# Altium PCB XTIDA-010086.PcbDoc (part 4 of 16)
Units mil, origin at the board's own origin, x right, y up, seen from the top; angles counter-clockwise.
Board outline 14763.78 x 8267.72 mil, 6 copper layers (Top Layer, GND Layer, Signal Layer 1, Signal Layer 2, Power Layer, Bottom Layer), stack 62 mil thick; 1933 components, 1002 nets, 4886 pads, 6482 vias.
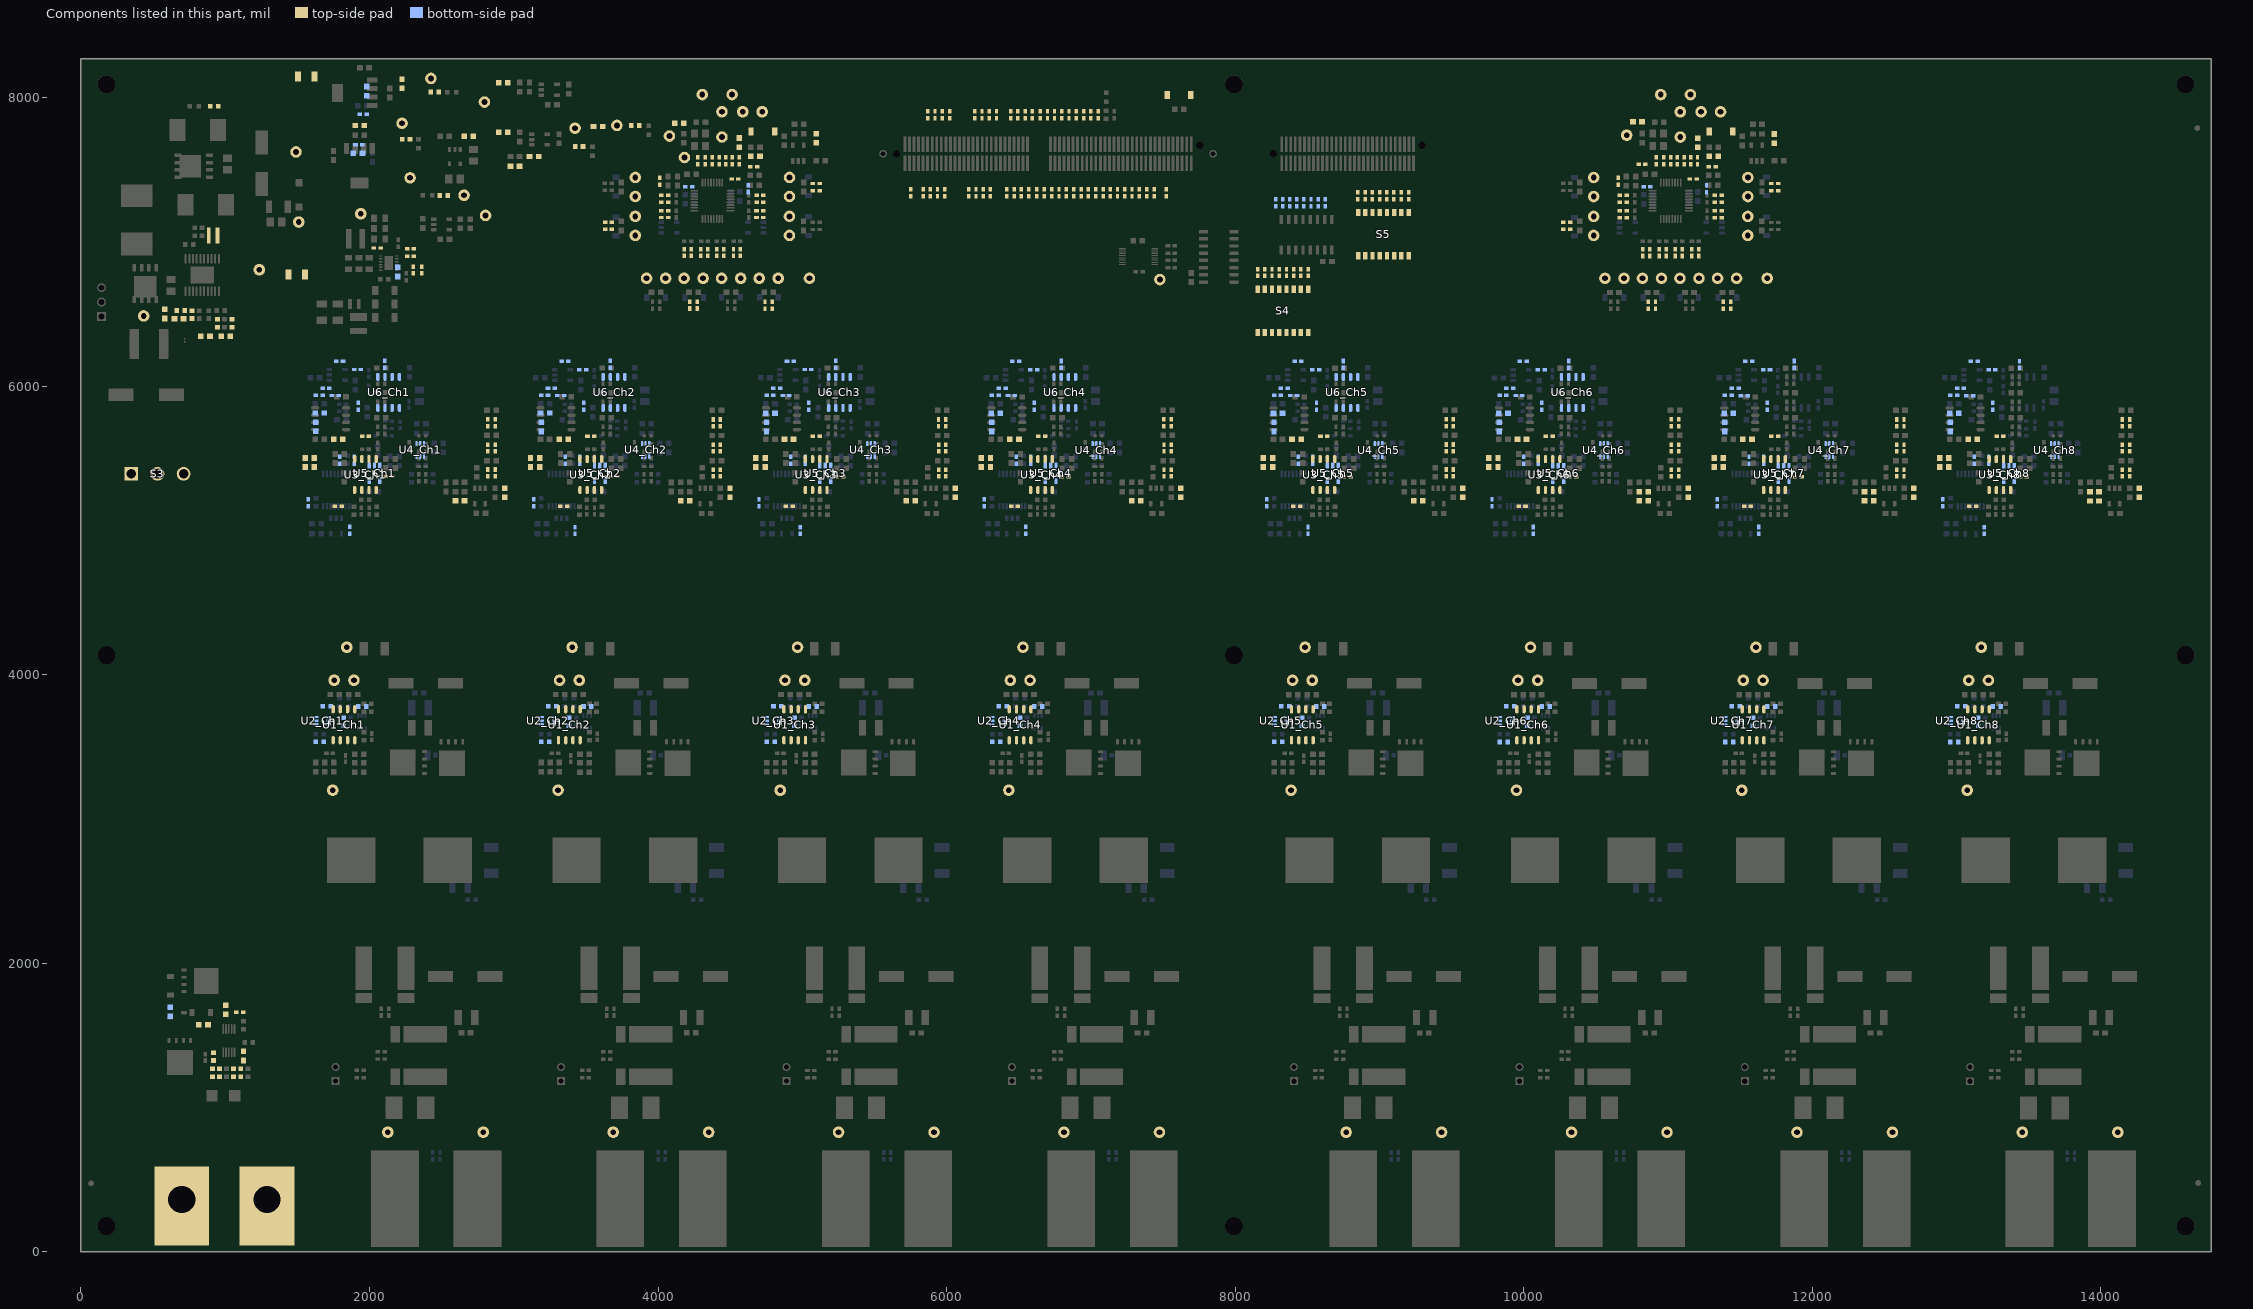
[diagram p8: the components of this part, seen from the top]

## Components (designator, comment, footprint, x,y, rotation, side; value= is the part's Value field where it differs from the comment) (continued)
R64_Ch6 "RT0603BRD07100KL" 0603 10831.24,5267.91 r0 top value=100k (schematic designator R64)
R64_Ch7 "RT0603BRD07100KL" 0603 12393.24,5267.83 r0 top value=100k (schematic designator R64)
R64_Ch8 "RT0603BRD07100KL" 0603 13955.24,5267.75 r0 top value=100k (schematic designator R64)
R65_Ch1 "PNM0402E5000BST1" 0402 2871,5398.08 r90 top value=500 (schematic designator R65)
R65_Ch2 "PNM0402E5000BST1" 0402 4432.54,5397.54 r90 top value=500 (schematic designator R65)
R65_Ch3 "PNM0402E5000BST1" 0402 5994.54,5397.46 r90 top value=500 (schematic designator R65)
R65_Ch4 "PNM0402E5000BST1" 0402 7556.6,5397.93 r90 top value=500 (schematic designator R65)
R65_Ch5 "PNM0402E5000BST1" 0402 9512.29,5398.24 r90 top value=500 (schematic designator R65)
R65_Ch6 "PNM0402E5000BST1" 0402 11073.3,5397.77 r90 top value=500 (schematic designator R65)
R65_Ch7 "PNM0402E5000BST1" 0402 12635.3,5397.69 r90 top value=500 (schematic designator R65)
R65_Ch8 "PNM0402E5000BST1" 0402 14198.3,5397.62 r90 top value=500 (schematic designator R65)
R66_Ch1 "PNM0402E5000BST1" 0402 2871,5571.08 r90 top value=500 (schematic designator R66)
R66_Ch2 "PNM0402E5000BST1" 0402 4432.54,5570.54 r90 top value=500 (schematic designator R66)
R66_Ch3 "PNM0402E5000BST1" 0402 5994.54,5570.46 r90 top value=500 (schematic designator R66)
R66_Ch4 "PNM0402E5000BST1" 0402 7556.6,5570.93 r90 top value=500 (schematic designator R66)
R66_Ch5 "PNM0402E5000BST1" 0402 9512.29,5571.24 r90 top value=500 (schematic designator R66)
R66_Ch6 "PNM0402E5000BST1" 0402 11073.3,5570.77 r90 top value=500 (schematic designator R66)
R66_Ch7 "PNM0402E5000BST1" 0402 12635.3,5570.69 r90 top value=500 (schematic designator R66)
R66_Ch8 "PNM0402E5000BST1" 0402 14198.3,5570.62 r90 top value=500 (schematic designator R66)
R67_Ch1 "PNM0402E5000BST1" 0402 2871,5745.08 r90 top value=500 (schematic designator R67)
R67_Ch2 "PNM0402E5000BST1" 0402 4432.54,5744.54 r90 top value=500 (schematic designator R67)
R67_Ch3 "PNM0402E5000BST1" 0402 5994.54,5744.46 r90 top value=500 (schematic designator R67)
R67_Ch4 "PNM0402E5000BST1" 0402 7556.6,5744.93 r90 top value=500 (schematic designator R67)
R67_Ch5 "PNM0402E5000BST1" 0402 9512.29,5745.24 r90 top value=500 (schematic designator R67)
R67_Ch6 "PNM0402E5000BST1" 0402 11073.3,5744.77 r90 top value=500 (schematic designator R67)
R67_Ch7 "PNM0402E5000BST1" 0402 12635.3,5744.69 r90 top value=500 (schematic designator R67)
R67_Ch8 "PNM0402E5000BST1" 0402 14198.3,5744.62 r90 top value=500 (schematic designator R67)
R68_Ch1 "PNM0402E5000BST1" 0402 3656.85,7085.68 r0 top value=500 (schematic designator R68)
R68_Ch2 "PNM0402E5000BST1" 0402 4271.03,6561.02 r90 top value=500 (schematic designator R68)
R68_Ch3 "PNM0402E5000BST1" 0402 4791.7,6560.09 r90 top value=500 (schematic designator R68)
R68_Ch4 "PNM0402E5000BST1" 0402 5097,7403.98 r180 top value=500 (schematic designator R68)
R68_Ch5 "PNM0402E5000BST1" 0402 10298.55,7085.37 r0 top value=500 (schematic designator R68)
R68_Ch6 "PNM0402E5000BST1" 0402 10912.73,6560.71 r90 top value=500 (schematic designator R68)
R68_Ch7 "PNM0402E5000BST1" 0402 11433.15,6560.71 r90 top value=500 (schematic designator R68)
R68_Ch8 "PNM0402E5000BST1" 0402 11738.7,7403.67 r180 top value=500 (schematic designator R68)
R69_Ch1 "CRCW06033K32FKEA" 0603 1628,5717.5 r270 bottom value=3.32k (schematic designator R69)
R69_Ch2 "CRCW06033K32FKEA" 0603 3189.55,5716.98 r270 bottom value=3.32k (schematic designator R69)
R69_Ch3 "CRCW06033K32FKEA" 0603 4751.55,5716.9 r270 bottom value=3.32k (schematic designator R69)
R69_Ch4 "CRCW06033K32FKEA" 0603 6313.55,5716.82 r270 bottom value=3.32k (schematic designator R69)
R69_Ch5 "CRCW06033K32FKEA" 0603 8269.25,5716.74 r270 bottom value=3.32k (schematic designator R69)
R69_Ch6 "CRCW06033K32FKEA" 0603 9831.25,5716.66 r270 bottom value=3.32k (schematic designator R69)
R69_Ch7 "CRCW06033K32FKEA" 0603 11393.25,5716.58 r270 bottom value=3.32k (schematic designator R69)
R69_Ch8 "CRCW06033K32FKEA" 0603 12955.7,5716.95 r270 bottom value=3.32k (schematic designator R69)
R70_Ch1 "RT0603BRD07100KL" 0603 2627.54,5204.3 r0 top value=100k (schematic designator R70)
R70_Ch2 "RT0603BRD07100KL" 0603 4189.54,5204.22 r0 top value=100k (schematic designator R70)
R70_Ch3 "RT0603BRD07100KL" 0603 5751.54,5204.14 r0 top value=100k (schematic designator R70)
R70_Ch4 "RT0603BRD07100KL" 0603 7313.54,5204.06 r0 top value=100k (schematic designator R70)
R70_Ch5 "RT0603BRD07100KL" 0603 9269.24,5203.98 r0 top value=100k (schematic designator R70)
R70_Ch6 "RT0603BRD07100KL" 0603 10831.24,5203.91 r0 top value=100k (schematic designator R70)
R70_Ch7 "RT0603BRD07100KL" 0603 12393.24,5203.83 r0 top value=100k (schematic designator R70)
R70_Ch8 "RT0603BRD07100KL" 0603 13955.24,5203.75 r0 top value=100k (schematic designator R70)
R71_Ch1 "PNM0402E5000BST1" 0402 2821,5398.08 r90 top value=500 (schematic designator R71)
R71_Ch2 "PNM0402E5000BST1" 0402 4382.54,5397.54 r90 top value=500 (schematic designator R71)
R71_Ch3 "PNM0402E5000BST1" 0402 5944.54,5397.46 r90 top value=500 (schematic designator R71)
R71_Ch4 "PNM0402E5000BST1" 0402 7506.6,5397.93 r90 top value=500 (schematic designator R71)
R71_Ch5 "PNM0402E5000BST1" 0402 9462.29,5398.24 r90 top value=500 (schematic designator R71)
R71_Ch6 "PNM0402E5000BST1" 0402 11023.3,5397.77 r90 top value=500 (schematic designator R71)
R71_Ch7 "PNM0402E5000BST1" 0402 12585.3,5397.69 r90 top value=500 (schematic designator R71)
R71_Ch8 "PNM0402E5000BST1" 0402 14148.3,5397.62 r90 top value=500 (schematic designator R71)
R72_Ch1 "PNM0402E5000BST1" 0402 2821,5571.08 r90 top value=500 (schematic designator R72)
R72_Ch2 "PNM0402E5000BST1" 0402 4382.54,5570.54 r90 top value=500 (schematic designator R72)
R72_Ch3 "PNM0402E5000BST1" 0402 5944.54,5570.46 r90 top value=500 (schematic designator R72)
R72_Ch4 "PNM0402E5000BST1" 0402 7506.6,5570.93 r90 top value=500 (schematic designator R72)
R72_Ch5 "PNM0402E5000BST1" 0402 9462.29,5571.24 r90 top value=500 (schematic designator R72)
R72_Ch6 "PNM0402E5000BST1" 0402 11023.3,5570.77 r90 top value=500 (schematic designator R72)
R72_Ch7 "PNM0402E5000BST1" 0402 12585.3,5570.69 r90 top value=500 (schematic designator R72)
R72_Ch8 "PNM0402E5000BST1" 0402 14148.3,5570.62 r90 top value=500 (schematic designator R72)
R73_Ch1 "PNM0402E5000BST1" 0402 2821,5745.08 r90 top value=500 (schematic designator R73)
R73_Ch2 "PNM0402E5000BST1" 0402 4382.09,5744.54 r90 top value=500 (schematic designator R73)
R73_Ch3 "PNM0402E5000BST1" 0402 5944.09,5744.46 r90 top value=500 (schematic designator R73)
R73_Ch4 "PNM0402E5000BST1" 0402 7506.14,5744.93 r90 top value=500 (schematic designator R73)
R73_Ch5 "PNM0402E5000BST1" 0402 9461.83,5745.24 r90 top value=500 (schematic designator R73)
R73_Ch6 "PNM0402E5000BST1" 0402 11022.84,5744.77 r90 top value=500 (schematic designator R73)
R73_Ch7 "PNM0402E5000BST1" 0402 12584.84,5744.69 r90 top value=500 (schematic designator R73)
R73_Ch8 "PNM0402E5000BST1" 0402 14147.84,5744.62 r90 top value=500 (schematic designator R73)
R74_Ch1 "PNM0402E5000BST1" 0402 3656.85,7136.14 r0 top value=500 (schematic designator R74)
R74_Ch2 "PNM0402E5000BST1" 0402 4220.57,6561.02 r90 top value=500 (schematic designator R74)
R74_Ch3 "PNM0402E5000BST1" 0402 4741.24,6560.09 r90 top value=500 (schematic designator R74)
R74_Ch4 "PNM0402E5000BST1" 0402 5097,7353.52 r180 top value=500 (schematic designator R74)
R74_Ch5 "PNM0402E5000BST1" 0402 10298.55,7135.82 r0 top value=500 (schematic designator R74)
R74_Ch6 "PNM0402E5000BST1" 0402 10862.27,6560.71 r90 top value=500 (schematic designator R74)
R74_Ch7 "PNM0402E5000BST1" 0402 11382.69,6560.71 r90 top value=500 (schematic designator R74)
R74_Ch8 "PNM0402E5000BST1" 0402 11738.7,7353.21 r180 top value=500 (schematic designator R74)
R75_Ch1 "CRCW060310K0FKEA" 0603 1784,5630.7 r180 top value=10.0k (schematic designator R75)
R75_Ch2 "CRCW060310K0FKEA" 0603 3346,5630.62 r180 top value=10.0k (schematic designator R75)
R75_Ch3 "CRCW060310K0FKEA" 0603 4908,5630.54 r180 top value=10.0k (schematic designator R75)
R75_Ch4 "CRCW060310K0FKEA" 0603 6470,5630.46 r180 top value=10.0k (schematic designator R75)
R75_Ch5 "CRCW060310K0FKEA" 0603 8425.7,5630.39 r180 top value=10.0k (schematic designator R75)
R75_Ch6 "CRCW060310K0FKEA" 0603 9987.7,5630.31 r180 top value=10.0k (schematic designator R75)
R75_Ch7 "CRCW060310K0FKEA" 0603 11549.7,5630.23 r180 top value=10.0k (schematic designator R75)
R75_Ch8 "CRCW060310K0FKEA" 0603 13111.7,5630.15 r180 top value=10.0k (schematic designator R75)
R76_Ch1 "CRCW040210K0FKED" 0402 1763,5934.7 r0 bottom value=10.0k (schematic designator R76)
R76_Ch2 "CRCW040210K0FKED" 0402 3325,5934.62 r0 bottom value=10.0k (schematic designator R76)
R76_Ch3 "CRCW040210K0FKED" 0402 4887,5934.54 r0 bottom value=10.0k (schematic designator R76)
R76_Ch4 "CRCW040210K0FKED" 0402 6449,5934.46 r0 bottom value=10.0k (schematic designator R76)
R76_Ch5 "CRCW040210K0FKED" 0402 8404.7,5934.39 r0 bottom value=10.0k (schematic designator R76)
R76_Ch6 "CRCW040210K0FKED" 0402 9966.7,5934.31 r0 bottom value=10.0k (schematic designator R76)
R76_Ch7 "CRCW040210K0FKED" 0402 11528.7,5934.23 r0 bottom value=10.0k (schematic designator R76)
R76_Ch8 "CRCW040210K0FKED" 0402 13090.7,5934.15 r0 bottom value=10.0k (schematic designator R76)
R77_Ch1 "RT0603BRD0724KL" 0603 2936.54,5260.68 r90 top value=24.0k (schematic designator R77)
R77_Ch2 "RT0603BRD0724KL" 0603 4498.54,5260.6 r90 top value=24.0k (schematic designator R77)
R77_Ch3 "RT0603BRD0724KL" 0603 6060.54,5260.52 r90 top value=24.0k (schematic designator R77)
R77_Ch4 "RT0603BRD0724KL" 0603 7622.54,5260.44 r90 top value=24.0k (schematic designator R77)
R77_Ch5 "RT0603BRD0724KL" 0603 9578.24,5260.36 r90 top value=24.0k (schematic designator R77)
R77_Ch6 "RT0603BRD0724KL" 0603 11140.24,5260.28 r90 top value=24.0k (schematic designator R77)
R77_Ch7 "RT0603BRD0724KL" 0603 12702.24,5260.2 r90 top value=24.0k (schematic designator R77)
R77_Ch8 "RT0603BRD0724KL" 0603 14264.24,5260.13 r90 top value=24.0k (schematic designator R77)
R78_Ch1 "CRCW060310K0FKEA" 0603 1655.21,5813.03 r0 bottom value=10.0k (schematic designator R78)
R78_Ch2 "CRCW060310K0FKEA" 0603 3217.21,5812.95 r0 bottom value=10.0k (schematic designator R78)
R78_Ch3 "CRCW060310K0FKEA" 0603 4779.21,5812.87 r0 bottom value=10.0k (schematic designator R78)
R78_Ch4 "CRCW060310K0FKEA" 0603 6341.21,5812.79 r0 bottom value=10.0k (schematic designator R78)
R78_Ch5 "CRCW060310K0FKEA" 0603 8296.91,5812.71 r0 bottom value=10.0k (schematic designator R78)
R78_Ch6 "CRCW060310K0FKEA" 0603 9858.91,5812.63 r0 bottom value=10.0k (schematic designator R78)
R78_Ch7 "CRCW060310K0FKEA" 0603 11420.91,5812.55 r0 bottom value=10.0k (schematic designator R78)
R78_Ch8 "CRCW060310K0FKEA" 0603 12982.91,5812.48 r0 bottom value=10.0k (schematic designator R78)
R79_Ch1 "CRCW040210K0FKED" 0402 1652,5935.7 r0 bottom value=10.0k (schematic designator R79)
R79_Ch2 "CRCW040210K0FKED" 0402 3214,5935.62 r0 bottom value=10.0k (schematic designator R79)
R79_Ch3 "CRCW040210K0FKED" 0402 4776,5935.54 r0 bottom value=10.0k (schematic designator R79)
R79_Ch4 "CRCW040210K0FKED" 0402 6338,5935.46 r0 bottom value=10.0k (schematic designator R79)
R79_Ch5 "CRCW040210K0FKED" 0402 8293.7,5935.39 r0 bottom value=10.0k (schematic designator R79)
R79_Ch6 "CRCW040210K0FKED" 0402 9855.7,5935.31 r0 bottom value=10.0k (schematic designator R79)
R79_Ch7 "CRCW040210K0FKED" 0402 11417.7,5935.23 r0 bottom value=10.0k (schematic designator R79)
R79_Ch8 "CRCW040210K0FKED" 0402 12979.7,5935.15 r0 bottom value=10.0k (schematic designator R79)
R80 "CRCW06032K00FKEA" 0603 849.33,1573.56 r180 top value=2.00k
R81 "RC0603FR-07330KL" 0603 620.09,1663.46 r90 bottom value=330k
R82 "RC0603FR-0710KL" 0603L 919.33,1353.56 r90 top value=10.0k
R83 "CRCW060320K5FKEA" 0603 1005,1677 r90 top value=20.5k
R84 "RC0603FR-0754K9L" 0603L 1058.33,1241.76 r270 top value=54.9k
R85 "RC0603FR-0762KL" 0603L 912.04,1241.76 r270 top value=62.0k
R86 "CRCW04020000Z0ED" 0402 1101,1659 r0 top value=0
R87 "CRCW06031M00FKEA" 0603 1127,1358 r270 top value=1.00Meg
R88 "RC0603FR-0710KL" 0603L 1107.83,1241.56 r90 top value=10.0k
R89 "RC0603FR-0710KL" 0603L 960.54,1241.76 r90 top value=10.0k
R90 "CRCW04020000Z0ED" 0402 4047.11,7321.51 r0 top value=0
R91 "CRCW04020000Z0ED" 0402 4047.11,7273.89 r0 top value=0
R92 "CRCW04020000Z0ED" 0402 4047.11,7216.33 r0 top value=0
R93 "CRCW04020000Z0ED" 0402 4047.11,7168.15 r0 top value=0
R94 "CRCW04020000Z0ED" 0402 4182.56,6925.39 r90 top value=0
R95 "CRCW04020000Z0ED" 0402 4275.11,7561.01 r90 top value=0
R96 "CRCW04020000Z0ED" 0402 4230.56,6925.39 r90 top value=0
R97 "CRCW04020000Z0ED" 0402 4328.11,7561.01 r90 top value=0
R98 "RC0603FR-07100KL" 0603 4146.89,7821.11 r180 top value=100k
R99 "CRCW04020000Z0ED" 0402 4297.56,6925.39 r90 top value=0
R100 "CRCW04020000Z0ED" 0402 4345.74,6925.39 r90 top value=0
R101 "CRCW04020000Z0ED" 0402 4407.56,6925.39 r90 top value=0
R102 "CRCW04020000Z0ED" 0402 4376.11,7561.01 r90 top value=0
R103 "CRCW04020000Z0ED" 0402 4455.74,6925.39 r90 top value=0
R104 "CRCW04020000Z0ED" 0402 4523.11,6925.39 r90 top value=0
R105 "CRCW04020000Z0ED" 0402 4423.11,7561.01 r90 top value=0
R106 "CRCW04020000Z0ED" 0402 4469.11,7561.01 r90 top value=0
R107 "CRCW04020000Z0ED" 0402 4571.3,6925.39 r90 top value=0
R108 "RC0603FR-07100KL" 0603 4563.11,7687.01 r90 top value=100k
R109 "RC0603FR-07100KL" 0603 4675.11,7592.01 r0 top value=100k
R110 "CRCW04020000Z0ED" 0402 4515.11,7561.01 r90 top value=0
R111 "CRCW04020000Z0ED" 0402 4706.18,7168.15 r180 top value=0
R112 "CRCW04020000Z0ED" 0402 4562.11,7561.01 r90 top value=0
R113 "CRCW04020000Z0ED" 0402 4706.18,7216.33 r180 top value=0
R114 "CRCW04020000Z0ED" 0402 4533.11,7435.01 r0 top value=0
R115 "CRCW04020000Z0ED" 0402 4212.53,7382.63 r180 bottom value=0
R116 "CRCW04020000Z0ED" 0402 4706.74,7273.89 r180 top value=0
R117 "CRCW04020000Z0ED" 0402 4706.74,7321.51 r180 top value=0
R118 "CRCW04020000Z0ED" 0402 4012.11,7419.01 r90 top value=0
R119 "CRCW04020000Z0ED" 0402 4624.53,7368.63 r270 bottom value=0
R120 "CRCW04020000Z0ED" 0402 4664.11,7520.01 r180 top value=0
R121 "CRCW04020000Z0ED" 0402 10688.82,7321.2 r0 top value=0
R122 "CRCW04020000Z0ED" 0402 10688.82,7273.57 r0 top value=0
R123 "CRCW04020000Z0ED" 0402 10688.82,7216.02 r0 top value=0
R124 "CRCW04020000Z0ED" 0402 10688.82,7167.84 r0 top value=0
R125 "CRCW04020000Z0ED" 0402 10824.26,6925.08 r90 top value=0
R126 "CRCW04020000Z0ED" 0402 10916.82,7560.7 r90 top value=0
R127 "CRCW04020000Z0ED" 0402 10872.26,6925.08 r90 top value=0
R128 "CRCW04020000Z0ED" 0402 10969.82,7560.7 r90 top value=0
R129 "RC0603FR-07100KL" 0603 10788,7831 r180 top value=100k
R130 "CRCW04020000Z0ED" 0402 10939.26,6925.08 r90 top value=0
R131 "CRCW04020000Z0ED" 0402 10987.44,6925.08 r90 top value=0
R132 "CRCW04020000Z0ED" 0402 11049.26,6925.08 r90 top value=0
R133 "CRCW04020000Z0ED" 0402 11017.82,7560.7 r90 top value=0
R134 "CRCW04020000Z0ED" 0402 11097.44,6925.08 r90 top value=0
R135 "CRCW04020000Z0ED" 0402 11164.82,6925.08 r90 top value=0
R136 "CRCW04020000Z0ED" 0402 11064.82,7560.7 r90 top value=0
R137 "CRCW04020000Z0ED" 0402 11110.82,7560.7 r90 top value=0
R138 "CRCW04020000Z0ED" 0402 11213,6925.08 r90 top value=0
R139 "RC0603FR-07100KL" 0603 11204.82,7686.7 r90 top value=100k
R140 "RC0603FR-07100KL" 0603 11316.82,7591.7 r0 top value=100k
R141 "CRCW04020000Z0ED" 0402 11156.82,7560.7 r90 top value=0
R142 "CRCW04020000Z0ED" 0402 11347.88,7167.83 r180 top value=0
R143 "CRCW04020000Z0ED" 0402 11203.82,7560.7 r90 top value=0
R144 "CRCW04020000Z0ED" 0402 11347.88,7216.02 r180 top value=0
R145 "CRCW04020000Z0ED" 0402 11174.82,7434.7 r0 top value=0
R146 "CRCW04020000Z0ED" 0402 10854.44,7382.11 r180 bottom value=0
R147 "CRCW04020000Z0ED" 0402 11348.44,7273.57 r180 top value=0
R148 "CRCW04020000Z0ED" 0402 11348.44,7321.2 r180 top value=0
R149 "CRCW04020000Z0ED" 0402 10653.82,7418.7 r90 top value=0
R150 "CRCW04020000Z0ED" 0402 11266.23,7368.32 r270 bottom value=0
R151 "CRCW04020000Z0ED" 0402 11305.82,7519.7 r180 top value=0
R152 "5108" 5108 1561.7,8145 r0 top value=0
R153 "5108" 5108 1496,6773.7 r180 top value=0
R159_Ch1 "CRCW04020000Z0ED" 0402 1576,5191 r90 bottom value=0 (schematic designator R159)
R159_Ch2 "CRCW04020000Z0ED" 0402 3138,5190.92 r90 bottom value=0 (schematic designator R159)
R159_Ch3 "CRCW04020000Z0ED" 0402 4700,5190.84 r90 bottom value=0 (schematic designator R159)
R159_Ch4 "CRCW04020000Z0ED" 0402 6262,5190.76 r90 bottom value=0 (schematic designator R159)
R159_Ch5 "CRCW04020000Z0ED" 0402 8217.7,5190.69 r90 bottom value=0 (schematic designator R159)
R159_Ch6 "CRCW04020000Z0ED" 0402 9779.7,5190.61 r90 bottom value=0 (schematic designator R159)
R159_Ch7 "CRCW04020000Z0ED" 0402 11341.7,5190.53 r90 bottom value=0 (schematic designator R159)
R159_Ch8 "CRCW04020000Z0ED" 0402 12903.7,5190.45 r90 bottom value=0 (schematic designator R159)
R160_Ch1 "CRCW04020000Z0ED" 0402 1863,5000 r90 bottom value=0 (schematic designator R160)
R160_Ch2 "CRCW04020000Z0ED" 0402 3424.49,4999.41 r90 bottom value=0 (schematic designator R160)
R160_Ch3 "CRCW04020000Z0ED" 0402 4986.49,4999.33 r90 bottom value=0 (schematic designator R160)
R160_Ch4 "CRCW04020000Z0ED" 0402 6549,4999.76 r90 bottom value=0 (schematic designator R160)
R160_Ch5 "CRCW04020000Z0ED" 0402 8504.7,4999.69 r90 bottom value=0 (schematic designator R160)
R160_Ch6 "CRCW04020000Z0ED" 0402 10066.7,4999.61 r90 bottom value=0 (schematic designator R160)
R160_Ch7 "CRCW04020000Z0ED" 0402 11628.7,4999.53 r90 bottom value=0 (schematic designator R160)
R160_Ch8 "CRCW04020000Z0ED" 0402 13190.19,4998.94 r90 bottom value=0 (schematic designator R160)
R161_Ch1 "CRCW04020000Z0ED" 0402 1795.38,5485.62 r270 bottom value=0 (schematic designator R161)
R161_Ch2 "CRCW04020000Z0ED" 0402 3357.38,5485.54 r270 bottom value=0 (schematic designator R161)
R161_Ch3 "CRCW04020000Z0ED" 0402 4919.38,5485.46 r270 bottom value=0 (schematic designator R161)
R161_Ch4 "CRCW04020000Z0ED" 0402 6481.38,5485.39 r270 bottom value=0 (schematic designator R161)
R161_Ch5 "CRCW04020000Z0ED" 0402 8437.08,5485.31 r270 bottom value=0 (schematic designator R161)
R161_Ch6 "CRCW04020000Z0ED" 0402 9999.08,5485.23 r270 bottom value=0 (schematic designator R161)
R161_Ch7 "CRCW04020000Z0ED" 0402 11561.08,5485.15 r270 bottom value=0 (schematic designator R161)
R161_Ch8 "CRCW04020000Z0ED" 0402 13123.08,5485.07 r270 bottom value=0 (schematic designator R161)
R162_Ch1 "CRCW040210K0FKED" 0402 1784.76,5166.8 r180 top value=10.0k (schematic designator R162)
R162_Ch2 "CRCW040210K0FKED" 0402 3346.76,5166.72 r180 top value=10.0k (schematic designator R162)
R162_Ch3 "CRCW040210K0FKED" 0402 4908.76,5166.64 r180 top value=10.0k (schematic designator R162)
R162_Ch4 "CRCW040210K0FKED" 0402 6470.76,5166.56 r180 top value=10.0k (schematic designator R162)
R162_Ch5 "CRCW040210K0FKED" 0402 8426.46,5166.48 r180 top value=10.0k (schematic designator R162)
R162_Ch6 "CRCW040210K0FKED" 0402 9988.46,5166.4 r180 top value=10.0k (schematic designator R162)
R162_Ch7 "CRCW040210K0FKED" 0402 11550.46,5166.32 r180 top value=10.0k (schematic designator R162)
R162_Ch8 "CRCW040210K0FKED" 0402 13112.46,5166.24 r180 top value=10.0k (schematic designator R162)
R163 "Resistor" 0603 2927,8103 r0 top value=0
R164 "CRCW04020000Z0ED" 0402 8279.7,7269.62 r90 bottom value=0
R165 "CRCW04020000Z0ED" 0402 8328.8,7269.62 r90 bottom value=0
R166 "CRCW04020000Z0ED" 0402 8377.9,7269.62 r90 bottom value=0
R167 "CRCW04020000Z0ED" 0402 8427,7269.62 r90 bottom value=0
R168 "CRCW04020000Z0ED" 0402 8476.1,7269.62 r90 bottom value=0
R169 "CRCW04020000Z0ED" 0402 8525.2,7269.62 r90 bottom value=0
R170 "CRCW04020000Z0ED" 0402 8574.3,7269.62 r90 bottom value=0
R171 "CRCW04020000Z0ED" 0402 8623.4,7269.62 r90 bottom value=0
R172_Ch1 "RC0603JR-070RL" 0603L 1657,3534.69 r180 bottom value=0 (schematic designator R172)
R172_Ch2 "RC0603JR-070RL" 0603L 3219,3534.61 r180 bottom value=0 (schematic designator R172)
R172_Ch3 "RC0603JR-070RL" 0603L 4781,3534.53 r180 bottom value=0 (schematic designator R172)
R172_Ch4 "RC0603JR-070RL" 0603L 6343,3534.45 r180 bottom value=0 (schematic designator R172)
R172_Ch5 "RC0603JR-070RL" 0603L 8298.7,3534.37 r180 bottom value=0 (schematic designator R172)
R172_Ch6 "RC0603JR-070RL" 0603L 9860.7,3534.29 r180 bottom value=0 (schematic designator R172)
R172_Ch7 "RC0603JR-070RL" 0603L 11422.7,3534.21 r180 bottom value=0 (schematic designator R172)
R172_Ch8 "RC0603JR-070RL" 0603L 12984.7,3534.13 r180 bottom value=0 (schematic designator R172)
R173_Ch1 "RC0603FR-0710KL" 0603 1554,5470.5 r90 top value=10.0k (schematic designator R173)
R173_Ch2 "RC0603FR-0710KL" 0603 3116,5470.42 r90 top value=10.0k (schematic designator R173)
R173_Ch3 "RC0603FR-0710KL" 0603 4678,5470.34 r90 top value=10.0k (schematic designator R173)
R173_Ch4 "RC0603FR-0710KL" 0603 6240,5470.26 r90 top value=10.0k (schematic designator R173)
R173_Ch5 "RC0603FR-0710KL" 0603 8195.7,5470.18 r90 top value=10.0k (schematic designator R173)
R173_Ch6 "RC0603FR-0710KL" 0603 9757.7,5470.1 r90 top value=10.0k (schematic designator R173)
R173_Ch7 "RC0603FR-0710KL" 0603 11319.7,5470.02 r90 top value=10.0k (schematic designator R173)
R173_Ch8 "RC0603FR-0710KL" 0603 12881.7,5469.95 r90 top value=10.0k (schematic designator R173)
R174_Ch1 "RC0603FR-0710KL" 0603 1618,5470.5 r90 top value=10.0k (schematic designator R174)
R174_Ch2 "RC0603FR-0710KL" 0603 3180,5470.42 r90 top value=10.0k (schematic designator R174)
R174_Ch3 "RC0603FR-0710KL" 0603 4742,5470.34 r90 top value=10.0k (schematic designator R174)
R174_Ch4 "RC0603FR-0710KL" 0603 6304,5470.26 r90 top value=10.0k (schematic designator R174)
R174_Ch5 "RC0603FR-0710KL" 0603 8259.7,5470.18 r90 top value=10.0k (schematic designator R174)
R174_Ch6 "RC0603FR-0710KL" 0603 9821.7,5470.1 r90 top value=10.0k (schematic designator R174)
R174_Ch7 "RC0603FR-0710KL" 0603 11383.7,5470.02 r90 top value=10.0k (schematic designator R174)
R174_Ch8 "RC0603FR-0710KL" 0603 12945.7,5469.95 r90 top value=10.0k (schematic designator R174)
R175_Ch1 "CRCW04020000Z0ED" 0402 1973,5653.35 r0 top value=0 (schematic designator R175)
R175_Ch2 "CRCW04020000Z0ED" 0402 3535,5653.28 r0 top value=0 (schematic designator R175)
R175_Ch3 "CRCW04020000Z0ED" 0402 5097,5653.2 r0 top value=0 (schematic designator R175)
R175_Ch4 "CRCW04020000Z0ED" 0402 6659,5653.12 r0 top value=0 (schematic designator R175)
R175_Ch5 "CRCW04020000Z0ED" 0402 8614.7,5653.04 r0 top value=0 (schematic designator R175)
R175_Ch6 "CRCW04020000Z0ED" 0402 10176.7,5652.96 r0 top value=0 (schematic designator R175)
R175_Ch7 "CRCW04020000Z0ED" 0402 11738.7,5652.88 r0 top value=0 (schematic designator R175)
R175_Ch8 "CRCW04020000Z0ED" 0402 13300.7,5652.8 r0 top value=0 (schematic designator R175)
R176 "Resistor" 0603 2225.83,8095 r90 top value=0
R177 "RC0603FR-07100KL" 0603 5096,7717 r90 top value=100k
R178 "CRCW06034K99FKEA" 0603L 2515,7321.32 r180 top value=4.99k
R179 "CRCW06034K99FKEA" 0603L 3842,7805 r0 top value=4.99k
R180 "CRCW06034K99FKEA" 0603L 3452.56,7660 r0 top value=4.99k
R181 "RC0603FR-07100KL" 0603 11737.06,7715.29 r90 top value=100k
R182 "CRCW06034K99FKEA" 0603L 2253.56,7710.56 r0 top value=4.99k
R183 "CRCW06034K99FKEA" 0603L 2453,8037 r0 top value=4.99k
R184 "CRCW0603100KFKEA" 0603 2689,7731.32 r0 top value=100k
R185_Ch1 "CRCW04020000Z0ED" 0402 2135.79,5373 r180 top value=0 (schematic designator R185)
R185_Ch2 "CRCW04020000Z0ED" 0402 3697.79,5372.92 r180 top value=0 (schematic designator R185)
R185_Ch3 "CRCW04020000Z0ED" 0402 5259.79,5372.84 r180 top value=0 (schematic designator R185)
R185_Ch4 "CRCW04020000Z0ED" 0402 6821.79,5372.76 r180 top value=0 (schematic designator R185)
R185_Ch5 "CRCW04020000Z0ED" 0402 8777.49,5372.69 r180 top value=0 (schematic designator R185)
R185_Ch6 "CRCW04020000Z0ED" 0402 10339.49,5372.61 r180 top value=0 (schematic designator R185)
R185_Ch7 "CRCW04020000Z0ED" 0402 11901.49,5372.53 r180 top value=0 (schematic designator R185)
R185_Ch8 "CRCW04020000Z0ED" 0402 13463.49,5372.45 r180 top value=0 (schematic designator R185)
R186_Ch1 "CRCW04020000Z0ED" 0402 2107,6151.38 r90 bottom value=0 (schematic designator R186)
R186_Ch2 "CRCW04020000Z0ED" 0402 3670,6150.3 r90 bottom value=0 (schematic designator R186)
R186_Ch3 "CRCW04020000Z0ED" 0402 5232,6150.22 r90 bottom value=0 (schematic designator R186)
R186_Ch4 "CRCW04020000Z0ED" 0402 6794,6150.14 r90 bottom value=0 (schematic designator R186)
R186_Ch5 "CRCW04020000Z0ED" 0402 8749.7,6150.06 r90 bottom value=0 (schematic designator R186)
R186_Ch6 "CRCW04020000Z0ED" 0402 10311.7,6149.98 r90 bottom value=0 (schematic designator R186)
R186_Ch7 "CRCW04020000Z0ED" 0402 11873.7,6149.91 r90 bottom value=0 (schematic designator R186)
R186_Ch8 "CRCW04020000Z0ED" 0402 13435.7,6149.83 r90 bottom value=0 (schematic designator R186)
R187 "CRCW04020000Z0ED" 0402 10819,7536.86 r180 top value=0
R188 "CRCW04020000Z0ED" 0402 1927,7673 r0 bottom value=0
R189 "CRCW04020000Z0ED" 0402 1957,7883 r0 bottom value=0
R190 "RC0603FR-0710KL" 0603 1920,7614 r180 bottom value=10.0k
R191 "RC0603FR-0710KL" 0603 1982,8044 r90 bottom value=10.0k
R192_Ch1 "CRCW04020000Z0ED" 0402 1922,5861 r270 bottom value=0 (schematic designator R192)
R192_Ch2 "CRCW04020000Z0ED" 0402 3484,5860.92 r270 bottom value=0 (schematic designator R192)
R192_Ch3 "CRCW04020000Z0ED" 0402 5046,5860.84 r270 bottom value=0 (schematic designator R192)
R192_Ch4 "CRCW04020000Z0ED" 0402 6608,5860.76 r270 bottom value=0 (schematic designator R192)
R192_Ch5 "CRCW04020000Z0ED" 0402 8563.7,5860.69 r270 bottom value=0 (schematic designator R192)
R192_Ch6 "CRCW04020000Z0ED" 0402 10125.7,5860.61 r270 bottom value=0 (schematic designator R192)
R192_Ch7 "CRCW04020000Z0ED" 0402 11687.7,5860.53 r270 bottom value=0 (schematic designator R192)
R192_Ch8 "CRCW04020000Z0ED" 0402 13249.7,5860.45 r270 bottom value=0 (schematic designator R192)
R193_Ch1 "CRCW04020000Z0ED" 0402 1896,5486 r270 bottom value=0 (schematic designator R193)
R193_Ch2 "CRCW04020000Z0ED" 0402 3458,5485.92 r270 bottom value=0 (schematic designator R193)
R193_Ch3 "CRCW04020000Z0ED" 0402 5020,5485.84 r270 bottom value=0 (schematic designator R193)
R193_Ch4 "CRCW04020000Z0ED" 0402 6582,5485.76 r270 bottom value=0 (schematic designator R193)
R193_Ch5 "CRCW04020000Z0ED" 0402 8537.32,5485.31 r270 bottom value=0 (schematic designator R193)
R193_Ch6 "CRCW04020000Z0ED" 0402 10099.7,5485.61 r270 bottom value=0 (schematic designator R193)
R193_Ch7 "CRCW04020000Z0ED" 0402 11661.7,5485.53 r270 bottom value=0 (schematic designator R193)
R193_Ch8 "CRCW04020000Z0ED" 0402 13223.7,5485.45 r270 bottom value=0 (schematic designator R193)
R194 "RC0603FR-0710KL" 0603 3009,7523.7 r0 top value=10.0k
R195 "RC0603FR-0710KL" 0603 2197,6791 r90 bottom value=10.0k
R196 "CRCW040249R9FKED" 0402 2055,6957 r0 top value=49.9
R197 "CRCW0402130KFKED" 0402 2285,6901 r0 top value=130k
R198 "CRCW0402100KDHEDP" 0402 2305,6804 r270 top value=100k
R199 "CRCW040224K0JNED" 0402 2285,6951 r180 top value=24k
R200 "CRCW0402100KDHEDP" 0402 2362,6804 r270 top value=100k
R201 "Resistor" 0603 2927,7757.7 r0 top value=0
R202 "CRCW0603100KFKEA" 0603 3141.03,7590.93 r0 top value=100k
R203 "Resistor" 0603 3584.5,7799 r0 top value=0
R204_Ch1 "CRCW040210K0FKED" 0402 1793.24,6173.24 r0 bottom value=10.0k (schematic designator R204)
R204_Ch2 "CRCW040210K0FKED" 0402 3355.49,6172.91 r0 bottom value=10.0k (schematic designator R204)
R204_Ch3 "CRCW040210K0FKED" 0402 4917.49,6172.83 r0 bottom value=10.0k (schematic designator R204)
R204_Ch4 "CRCW040210K0FKED" 0402 6479.49,6172.76 r0 bottom value=10.0k (schematic designator R204)
R204_Ch5 "CRCW040210K0FKED" 0402 8435.19,6172.68 r0 bottom value=10.0k (schematic designator R204)
R204_Ch6 "CRCW040210K0FKED" 0402 9997.19,6172.6 r0 bottom value=10.0k (schematic designator R204)
R204_Ch7 "CRCW040210K0FKED" 0402 11559.19,6172.52 r0 bottom value=10.0k (schematic designator R204)
R204_Ch8 "CRCW040210K0FKED" 0402 13121.19,6172.44 r0 bottom value=10.0k (schematic designator R204)
R205 "Resistor" 0603 1933,7806 r0 top value=0
R206 "CRCW060320K0FKEA" 0603L 693.5,6524.7 r0 top value=20.0k
R207 "RC0603FR-07100KL" 0603 581.5,6499.7 r90 top value=100k
R208 "CRCW060349K9FKEA" 0603 680.5,6467.7 r180 top value=49.9k
R209 "CRCW06034K99FKEA" 0603L 924,7938.7 r180 top value=4.99k
R210 "CRCW060318K2FKEA" 0603L 771.3,6495.9 r90 top value=18.2k
R211 "PRL1632-R068-F-T1" 0612 916,7043.7 r0 top value=0.068
R212 "RC0603FR-0724KL" 0603L 947.71,6435.9 r270 top value=24.0k
R213 "RC0603FR-077K32L" 0603 863,6345.7 r0 top value=7.32k
R214 "RC0603FR-0752K3L" 0603 1003.5,6345.7 r0 top value=52.3k
R215 "CRCW060310R0FKEA" 0603L 1047.5,6435.9 r90 top value=10.0
R216_Ch1 "RC0603JR-070RL" 0603L 1949.05,3779.11 r0 bottom value=0 (schematic designator R216)
R216_Ch2 "RC0603JR-070RL" 0603L 3511.05,3779.04 r0 bottom value=0 (schematic designator R216)
R216_Ch3 "RC0603JR-070RL" 0603L 5073.05,3778.96 r0 bottom value=0 (schematic designator R216)
R216_Ch4 "RC0603JR-070RL" 0603L 6635.05,3778.88 r0 bottom value=0 (schematic designator R216)
R216_Ch5 "RC0603JR-070RL" 0603L 8590.75,3778.8 r0 bottom value=0 (schematic designator R216)
R216_Ch6 "RC0603JR-070RL" 0603L 10152.75,3778.72 r0 bottom value=0 (schematic designator R216)
R216_Ch7 "RC0603JR-070RL" 0603L 11714.75,3778.64 r0 bottom value=0 (schematic designator R216)
R216_Ch8 "RC0603JR-070RL" 0603L 13276.75,3778.56 r0 bottom value=0 (schematic designator R216)
R217_Ch1 "RC0603JR-070RL" 0603L 1703.83,3781.39 r180 bottom value=0 (schematic designator R217)
R217_Ch2 "RC0603JR-070RL" 0603L 3265.83,3781.31 r180 bottom value=0 (schematic designator R217)
R217_Ch3 "RC0603JR-070RL" 0603L 4827.83,3781.23 r180 bottom value=0 (schematic designator R217)
R217_Ch4 "RC0603JR-070RL" 0603L 6389.83,3781.15 r180 bottom value=0 (schematic designator R217)
R217_Ch5 "RC0603JR-070RL" 0603L 8345.53,3781.08 r180 bottom value=0 (schematic designator R217)
R217_Ch6 "RC0603JR-070RL" 0603L 9907.53,3781 r180 bottom value=0 (schematic designator R217)
R217_Ch7 "RC0603JR-070RL" 0603L 11469.53,3780.92 r180 bottom value=0 (schematic designator R217)
R217_Ch8 "RC0603JR-070RL" 0603L 13031.53,3780.84 r180 bottom value=0 (schematic designator R217)
R218_Ch1 "CRCW040210K0FKED" 0402 1916.98,6114.64 r0 bottom value=10.0k (schematic designator R218)
R218_Ch2 "CRCW040210K0FKED" 0402 3479.22,6114.31 r0 bottom value=10.0k (schematic designator R218)
R218_Ch3 "CRCW040210K0FKED" 0402 5039.33,6114.71 r0 bottom value=10.0k (schematic designator R218)
R218_Ch4 "CRCW040210K0FKED" 0402 6603.22,6114.16 r0 bottom value=10.0k (schematic designator R218)
R218_Ch5 "CRCW040210K0FKED" 0402 8559,6114 r0 bottom value=10.0k (schematic designator R218)
R218_Ch6 "CRCW040210K0FKED" 0402 10121,6113.92 r0 bottom value=10.0k (schematic designator R218)
R218_Ch7 "CRCW040210K0FKED" 0402 11682.92,6113.92 r0 bottom value=10.0k (schematic designator R218)
R218_Ch8 "CRCW040210K0FKED" 0402 13244.92,6113.84 r0 bottom value=10.0k (schematic designator R218)
R219_Ch1 "CRCW04020000Z0ED" 0402 1699,5985 r180 bottom value=0 (schematic designator R219)
R219_Ch2 "CRCW04020000Z0ED" 0402 3261.24,5984.68 r180 bottom value=0 (schematic designator R219)
R219_Ch3 "CRCW04020000Z0ED" 0402 4823.24,5984.6 r180 bottom value=0 (schematic designator R219)
R219_Ch4 "CRCW04020000Z0ED" 0402 6385.24,5984.52 r180 bottom value=0 (schematic designator R219)
R219_Ch5 "CRCW04020000Z0ED" 0402 8340.94,5984.44 r180 bottom value=0 (schematic designator R219)
R219_Ch6 "CRCW04020000Z0ED" 0402 9902.94,5984.36 r180 bottom value=0 (schematic designator R219)
R219_Ch7 "CRCW04020000Z0ED" 0402 11464.94,5984.28 r180 bottom value=0 (schematic designator R219)
R219_Ch8 "CRCW04020000Z0ED" 0402 13026.94,5984.2 r180 bottom value=0 (schematic designator R219)
R220_Ch1 "RC0603JR-070RL" 0603L 1822,3674.62 r90 bottom value=0 (schematic designator R220)
R220_Ch2 "RC0603JR-070RL" 0603L 3384,3674.54 r90 bottom value=0 (schematic designator R220)
R220_Ch3 "RC0603JR-070RL" 0603L 4946,3674.46 r90 bottom value=0 (schematic designator R220)
R220_Ch4 "RC0603JR-070RL" 0603L 6508,3674.38 r90 bottom value=0 (schematic designator R220)
R220_Ch5 "RC0603JR-070RL" 0603L 8463.7,3674.3 r90 bottom value=0 (schematic designator R220)
R220_Ch6 "RC0603JR-070RL" 0603L 10025.7,3674.23 r90 bottom value=0 (schematic designator R220)
R220_Ch7 "RC0603JR-070RL" 0603L 11587.7,3674.15 r90 bottom value=0 (schematic designator R220)
R220_Ch8 "RC0603JR-070RL" 0603L 13149.7,3674.07 r90 bottom value=0 (schematic designator R220)
R221 "CRCW04020000Z0ED" 0402 5751.74,7339.35 r90 top value=0
R223 "CRCW040210K0FKED" 0402 8505.35,6786.55 r270 top value=10.0k
R224 "CRCW040210K0FKED" 0402 8454.35,6786.55 r270 top value=10.0k
R225 "CRCW040210K0FKED" 0402 8405.35,6786.55 r270 top value=10.0k
R226 "CRCW040210K0FKED" 0402 8355.35,6786.55 r270 top value=10.0k
R227 "CRCW040210K0FKED" 0402 8305.35,6786.55 r270 top value=10.0k
R228 "CRCW040210K0FKED" 0402 8255.35,6786.55 r270 top value=10.0k
R229 "CRCW040210K0FKED" 0402 8205.35,6786.55 r270 top value=10.0k
R230 "CRCW040210K0FKED" 0402 8155.35,6786.55 r270 top value=10.0k
R231 "CRCW040210K0FKED" 0402 9201.86,7318.54 r270 top value=10.0k
R232 "CRCW040210K0FKED" 0402 9150.72,7318.54 r270 top value=10.0k
R233 "CRCW040210K0FKED" 0402 9099.86,7318.54 r270 top value=10.0k
R234 "CRCW040210K0FKED" 0402 9049.86,7318.54 r270 top value=10.0k
R235 "CRCW040210K0FKED" 0402 9000.86,7318.54 r270 top value=10.0k
R236 "CRCW040210K0FKED" 0402 8950.86,7318.54 r270 top value=10.0k
R237 "CRCW040210K0FKED" 0402 8900.86,7318.54 r270 top value=10.0k
R238 "CRCW040210K0FKED" 0402 8849.86,7318.54 r270 top value=10.0k
R245 "CRCW04020000Z0ED" 0402 5837.25,7339.35 r90 top value=0
R246 "CRCW04020000Z0ED" 0402 5887.06,7339.35 r90 top value=0
R247 "CRCW04020000Z0ED" 0402 5868.74,7879.92 r270 top value=0
R248 "CRCW04020000Z0ED" 0402 5919.39,7879.92 r270 top value=0
R249 "CRCW04020000Z0ED" 0402 5936.87,7339.35 r90 top value=0
R250 "CRCW04020000Z0ED" 0402 5986.68,7339.35 r90 top value=0
R251 "CRCW04020000Z0ED" 0402 5970.03,7879.92 r270 top value=0
R252 "CRCW04020000Z0ED" 0402 6020.68,7879.92 r270 top value=0
R253 "CRCW04020000Z0ED" 0402 6153.68,7339.35 r90 top value=0
R254 "CRCW04020000Z0ED" 0402 6203.68,7339.35 r90 top value=0
R255 "CRCW04020000Z0ED" 0402 6194.68,7879.92 r270 top value=0
R256 "CRCW04020000Z0ED" 0402 6245.01,7879.92 r270 top value=0
R257 "CRCW04020000Z0ED" 0402 6253.68,7339.35 r90 top value=0
R258 "CRCW04020000Z0ED" 0402 6303.68,7339.35 r90 top value=0
R259 "CRCW04020000Z0ED" 0402 6295.35,7879.92 r270 top value=0
R260 "CRCW04020000Z0ED" 0402 6345.68,7879.92 r270 top value=0
R261 "CRCW04020000Z0ED" 0402 6417.68,7339.35 r90 top value=0
R262 "CRCW04020000Z0ED" 0402 6443.89,7879.92 r270 top value=0
R263 "CRCW04020000Z0ED" 0402 6468.01,7339.5 r90 top value=0
R264 "CRCW04020000Z0ED" 0402 6494.15,7879.92 r270 top value=0
R265 "CRCW04020000Z0ED" 0402 6518.35,7339.5 r90 top value=0
R266 "CRCW04020000Z0ED" 0402 6544.42,7879.92 r270 top value=0
R267 "CRCW04020000Z0ED" 0402 6568.68,7339.5 r90 top value=0
R268 "CRCW04020000Z0ED" 0402 6594.68,7879.92 r270 top value=0
R269 "CRCW04020000Z0ED" 0402 6624.68,7339.5 r90 top value=0
R270 "CRCW04020000Z0ED" 0402 7285,7340 r270 top value=0
R271 "CRCW04020000Z0ED" 0402 6676.01,7339.5 r90 top value=0
R272 "CRCW04020000Z0ED" 0402 7235,7340 r270 top value=0
R273 "CRCW04020000Z0ED" 0402 6727.35,7339.5 r90 top value=0
R274 "CRCW04020000Z0ED" 0402 6797,7879.92 r270 top value=0
R275 "CRCW04020000Z0ED" 0402 6778.68,7339.5 r90 top value=0
R276 "CRCW04020000Z0ED" 0402 6983,7339.5 r270 top value=0
R277 "FC0402E50R0BST1" 0402 6830.01,7339.5 r90 top value=50
R278 "CRCW04020000Z0ED" 0402 6848.28,7879.7 r270 top value=0
R279 "FC0402E50R0BST1" 0402 6881.35,7339.5 r90 top value=50
R280 "FC0402E50R0BST1" 0402 6898.78,7879.7 r270 top value=50
R281 "CRCW04020000Z0ED" 0402 6932.68,7339.5 r90 top value=0
R282 "FC0402E50R0BST1" 0402 6949.28,7879.7 r270 top value=50
R283 "CRCW04020000Z0ED" 0402 6999.78,7879.7 r270 top value=0
R284 "FC0402E50R0BST1" 0402 7033.01,7339.5 r90 top value=50
R285 "FC0402E50R0BST1" 0402 7184.65,7340 r270 top value=50
R286 "FC0402E50R0BST1" 0402 7084.35,7339.5 r90 top value=50
R288 "FC0402E50R0BST1" 0402 7133,7340 r90 top value=50
R289 "CRCW04020000Z0ED" 0402 7052,7879.7 r270 top value=0
R292 "FC0402E50R0BST1" 0402 7336,7340 r90 top value=50
R293 "CRCW04020000Z0ED" 0402 6650,7879.92 r90 top value=0
R294 "CRCW04020000Z0ED" 0402 6699,7879.92 r90 top value=0
R295 "CRCW04020000Z0ED" 0402 6748,7879.92 r90 top value=0
R296 "CRCW04020000Z0ED" 0402 7521,7340 r90 top value=0
R297 "CRCW04020000Z0ED" 0402 7388,7340 r90 top value=0
R298 "FC0402E50R0BST1" 0402 7439,7340 r90 top value=50
S1 "Switch_PushButton" SW_TL1015AF160QG 4726.11,7765.01 r0 top
S2 "Switch_PushButton" SW_TL1015AF160QG 11367.82,7764.7 r0 top
S3 "L101011MS02Q" "SW_ L101011MS02Q" 531,5279 r90 top
S4 "218-8LPST" SW_218-8LP 8330.35,6520.55 r270 top
S5 "218-8LPST" SW_218-8LP 9026.86,7052.54 r270 top
S6 "Switch_PushButton" SW_TL1015AF160QG 7610.68,8017.7 r180 top
SH-J4 "60900213421" Wurth_60900213421 144,6544 r90 top
T1 "CB35-36-CY" CB35-36-CY 699.33,362.56 r90 top
T2 "CB35-36-CY" CB35-36-CY 1289.33,362.56 r90 top
TP1_Ch1 "5002" Keystone5002 1892.42,3961.11 r90 top (schematic designator TP1)
TP1_Ch2 "5002" Keystone5002 3454.42,3961.04 r90 top (schematic designator TP1)
TP1_Ch3 "5002" Keystone5002 5016.42,3960.96 r90 top (schematic designator TP1)
TP1_Ch4 "5002" Keystone5002 6578.42,3960.88 r90 top (schematic designator TP1)
TP1_Ch5 "5002" Keystone5002 8534.12,3960.8 r90 top (schematic designator TP1)
TP1_Ch6 "5002" Keystone5002 10096.12,3960.72 r90 top (schematic designator TP1)
TP1_Ch7 "5002" Keystone5002 11658.12,3960.64 r90 top (schematic designator TP1)
TP1_Ch8 "5002" Keystone5002 13220.12,3960.56 r90 top (schematic designator TP1)
TP2_Ch1 "5000" Keystone5000 1745.39,3199.31 r180 top (schematic designator TP2)
TP2_Ch2 "5000" Keystone5000 3307.39,3199.23 r180 top (schematic designator TP2)
TP2_Ch3 "5000" Keystone5000 4847.02,3198.86 r180 top (schematic designator TP2)
TP2_Ch4 "5000" Keystone5000 6431.39,3199.07 r180 top (schematic designator TP2)
TP2_Ch5 "5000" Keystone5000 8387.09,3198.99 r180 top (schematic designator TP2)
TP2_Ch6 "5000" Keystone5000 9949.09,3198.91 r180 top (schematic designator TP2)
TP2_Ch7 "5000" Keystone5000 11511.09,3198.83 r180 top (schematic designator TP2)
TP2_Ch8 "5000" Keystone5000 13073.09,3198.76 r180 top (schematic designator TP2)
TP3_Ch1 "5002" Keystone5002 1755.81,3961.11 r90 top (schematic designator TP3)
TP3_Ch2 "5002" Keystone5002 3317.81,3961.04 r90 top (schematic designator TP3)
TP3_Ch3 "5002" Keystone5002 4879.81,3960.96 r90 top (schematic designator TP3)
TP3_Ch4 "5002" Keystone5002 6441.81,3960.88 r90 top (schematic designator TP3)
TP3_Ch5 "5002" Keystone5002 8397.51,3960.8 r90 top (schematic designator TP3)
TP3_Ch6 "5002" Keystone5002 9959.51,3960.72 r90 top (schematic designator TP3)
TP3_Ch7 "5002" Keystone5002 11521.51,3960.64 r90 top (schematic designator TP3)
TP3_Ch8 "5002" Keystone5002 13083.51,3960.56 r90 top (schematic designator TP3)
TP4_Ch1 "5000" Keystone5000 1843,4190 r90 top (schematic designator TP4)
TP4_Ch2 "5000" Keystone5000 3405,4189.92 r90 top (schematic designator TP4)
TP4_Ch3 "5000" Keystone5000 4967,4189.84 r90 top (schematic designator TP4)
TP4_Ch4 "5000" Keystone5000 6529,4189.76 r90 top (schematic designator TP4)
TP4_Ch5 "5000" Keystone5000 8484.7,4189.69 r90 top (schematic designator TP4)
TP4_Ch6 "5000" Keystone5000 10046.7,4189.61 r90 top (schematic designator TP4)
TP4_Ch7 "5000" Keystone5000 11608.7,4189.53 r90 top (schematic designator TP4)
TP4_Ch8 "5000" Keystone5000 13170.7,4189.45 r90 top (schematic designator TP4)
TP5_Ch1 "5000" Keystone5000 2127.38,829 r90 top (schematic designator TP5)
TP5_Ch2 "5000" Keystone5000 3689.38,828.92 r90 top (schematic designator TP5)
TP5_Ch3 "5000" Keystone5000 5251.38,828.84 r90 top (schematic designator TP5)
TP5_Ch4 "5000" Keystone5000 6813.38,828.76 r90 top (schematic designator TP5)
TP5_Ch5 "5000" Keystone5000 8769.08,828.69 r90 top (schematic designator TP5)
TP5_Ch6 "5000" Keystone5000 10331.08,828.61 r90 top (schematic designator TP5)
TP5_Ch7 "5000" Keystone5000 11893.08,828.53 r90 top (schematic designator TP5)
TP5_Ch8 "5000" Keystone5000 13455.08,828.45 r90 top (schematic designator TP5)
TP6_Ch1 "5001" Keystone5001 2789,829 r90 top (schematic designator TP6)
TP6_Ch2 "5001" Keystone5001 4351,828.92 r90 top (schematic designator TP6)
TP6_Ch3 "5001" Keystone5001 5913,828.84 r90 top (schematic designator TP6)
TP6_Ch4 "5001" Keystone5001 7475,828.76 r90 top (schematic designator TP6)
TP6_Ch5 "5001" Keystone5001 9430.7,828.69 r90 top (schematic designator TP6)
TP6_Ch6 "5001" Keystone5001 10992.7,828.61 r90 top (schematic designator TP6)
TP6_Ch7 "5001" Keystone5001 12554.7,828.53 r90 top (schematic designator TP6)
TP6_Ch8 "5001" Keystone5001 14116.7,828.45 r90 top (schematic designator TP6)
TP7_Ch1 "5002" Keystone5002 3842.53,7445.63 r90 top (schematic designator TP7)
TP7_Ch2 "5002" Keystone5002 3920.75,6746.7 r180 top (schematic designator TP7)
TP7_Ch3 "5002" Keystone5002 4440.61,6746.7 r180 top (schematic designator TP7)
TP7_Ch4 "5002" Keystone5002 4910.76,7044.03 r270 top (schematic designator TP7)
TP7_Ch5 "5002" Keystone5002 10484.23,7445.32 r90 top (schematic designator TP7)
TP7_Ch6 "5002" Keystone5002 10562.45,6746.39 r180 top (schematic designator TP7)
TP7_Ch7 "5002" Keystone5002 11082.31,6746.39 r180 top (schematic designator TP7)
TP7_Ch8 "5002" Keystone5002 11552.47,7043.71 r270 top (schematic designator TP7)
TP8_Ch1 "5002" Keystone5002 3842.53,7313.63 r90 top (schematic designator TP8)
TP8_Ch2 "5002" Keystone5002 4052.75,6746.7 r180 top (schematic designator TP8)
TP8_Ch3 "5002" Keystone5002 4572.61,6746.7 r180 top (schematic designator TP8)
TP8_Ch4 "5002" Keystone5002 4910.76,7176.03 r270 top (schematic designator TP8)
TP8_Ch5 "5002" Keystone5002 10484.23,7313.32 r90 top (schematic designator TP8)
TP8_Ch6 "5002" Keystone5002 10694.45,6746.39 r180 top (schematic designator TP8)
TP8_Ch7 "5002" Keystone5002 11214.31,6746.39 r180 top (schematic designator TP8)
TP8_Ch8 "5002" Keystone5002 11552.47,7175.71 r270 top (schematic designator TP8)
TP9_Ch1 "5002" Keystone5002 3842.53,7044.03 r180 top (schematic designator TP9)
TP9_Ch2 "5002" Keystone5002 4312.68,6746.7 r270 top (schematic designator TP9)
TP9_Ch3 "5002" Keystone5002 4833.1,6746.7 r270 top (schematic designator TP9)
TP9_Ch4 "5002" Keystone5002 4911.32,7445.63 r0 top (schematic designator TP9)
TP9_Ch5 "5002" Keystone5002 10484.23,7043.71 r180 top (schematic designator TP9)
TP9_Ch6 "5002" Keystone5002 10954.38,6746.39 r270 top (schematic designator TP9)
TP9_Ch7 "5002" Keystone5002 11474.8,6746.39 r270 top (schematic designator TP9)
TP9_Ch8 "5002" Keystone5002 11553.02,7445.32 r0 top (schematic designator TP9)
TP10_Ch1 "5002" Keystone5002 3842.53,7176.03 r180 top (schematic designator TP10)
TP10_Ch2 "5002" Keystone5002 4180.68,6746.7 r270 top (schematic designator TP10)
TP10_Ch3 "5002" Keystone5002 4701.1,6746.7 r270 top (schematic designator TP10)
TP10_Ch4 "5002" Keystone5002 4911.32,7313.63 r0 top (schematic designator TP10)
TP10_Ch5 "5002" Keystone5002 10484.23,7175.71 r180 top (schematic designator TP10)
TP10_Ch6 "5002" Keystone5002 10822.38,6746.39 r270 top (schematic designator TP10)
TP10_Ch7 "5002" Keystone5002 11342.8,6746.39 r270 top (schematic designator TP10)
TP10_Ch8 "5002" Keystone5002 11553.02,7313.32 r0 top (schematic designator TP10)
TP11 "5002" Keystone5002 4183.11,7584.01 r180 top
TP12 "5002" Keystone5002 4307.11,8020.01 r180 top
TP13 "5002" Keystone5002 4443.11,7726.01 r180 top
TP14 "5002" Keystone5002 4443.11,7901.01 r180 top
TP15 "5002" Keystone5002 4513.49,8020.01 r180 top
TP16 "5002" Keystone5002 4587.11,7901.01 r180 top
TP17 "5002" Keystone5002 4722.11,7901.01 r180 top
TP18 "5002" Keystone5002 10948.82,8019.7 r180 top
TP19 "5002" Keystone5002 11084.82,7725.7 r180 top
TP20 "5002" Keystone5002 11084.82,7900.7 r180 top
TP21 "5002" Keystone5002 11155.19,8019.7 r180 top
TP22 "5002" Keystone5002 11228.82,7900.7 r180 top
TP23 "5002" Keystone5002 11363.82,7900.7 r180 top
TP24 "5000" Keystone5000 3425,7787 r90 top
TP25 "5000" Keystone5000 3715,7806 r180 top
TP26 "5000" Keystone5000 1940,7194 r180 top
TP27 "5000" Keystone5000 2226,7821 r90 top
TP28 "5000" Keystone5000 435.5,6485.7 r180 top
TP29 "5000" Keystone5000 1491,7622.7 r180 top
TP30 "5000" Keystone5000 2805,7182.7 r90 top
TP31 "5000" Keystone5000 2656,7322.32 r180 top
TP32 "5000" Keystone5000 1510.2,7136.69 r90 top
TP33 "5000" Keystone5000 2426,8132 r90 top
TP34 "5001" Keystone5001 1237,6806 r90 top
TP35 "5001" Keystone5001 2282,7443 r90 top
TP36 "5001" Keystone5001 2797,7968 r90 top
TP37 "5001" Keystone5001 5049.42,6746.7 r90 top
TP38 "5001" Keystone5001 4079,7732.42 r90 top
TP39 "5001" Keystone5001 11687,6746.39 r90 top
TP40 "5001" Keystone5001 10713,7738.62 r90 top
TP41 "5001" Keystone5001 7478,6738 r90 top
U1_Ch1 "LM5109BMAX/NOPB" D0008A_N 1823.37,3653.07 r270 top (schematic designator U1)
U1_Ch2 "LM5109BMAX/NOPB" D0008A_N 3385.37,3652.99 r270 top (schematic designator U1)
U1_Ch3 "LM5109BMAX/NOPB" D0008A_N 4947.37,3652.91 r270 top (schematic designator U1)
U1_Ch4 "LM5109BMAX/NOPB" D0008A_N 6509.37,3652.83 r270 top (schematic designator U1)
U1_Ch5 "LM5109BMAX/NOPB" D0008A_N 8465.07,3652.75 r270 top (schematic designator U1)
U1_Ch6 "LM5109BMAX/NOPB" D0008A_N 10027.07,3652.68 r270 top (schematic designator U1)
U1_Ch7 "LM5109BMAX/NOPB" D0008A_N 11589.07,3652.6 r270 top (schematic designator U1)
U1_Ch8 "LM5109BMAX/NOPB" D0008A_N 13151.07,3652.52 r270 top (schematic designator U1)
U2_Ch1 "SN74LVC1G11DCKR" DCK0006A_N 1674,3681 r180 bottom (schematic designator U2)
U2_Ch2 "SN74LVC1G11DCKR" DCK0006A_N 3236,3680.92 r180 bottom (schematic designator U2)
U2_Ch3 "SN74LVC1G11DCKR" DCK0006A_N 4798,3680.84 r180 bottom (schematic designator U2)
U2_Ch4 "SN74LVC1G11DCKR" DCK0006A_N 6360,3680.76 r180 bottom (schematic designator U2)
U2_Ch5 "SN74LVC1G11DCKR" DCK0006A_N 8315.7,3680.69 r180 bottom (schematic designator U2)
U2_Ch6 "SN74LVC1G11DCKR" DCK0006A_N 9877.7,3680.61 r180 bottom (schematic designator U2)
U2_Ch7 "SN74LVC1G11DCKR" DCK0006A_N 11439.7,3680.53 r180 bottom (schematic designator U2)
U2_Ch8 "SN74LVC1G11DCKR" DCK0006A_N 13001.7,3680.45 r180 bottom (schematic designator U2)
U3_Ch1 "INA821ID" D0008A_N 1972,5387.05 r90 top (schematic designator U3)
U3_Ch2 "INA821ID" D0008A_N 3534,5386.97 r90 top (schematic designator U3)
U3_Ch3 "INA821ID" D0008A_N 5096,5386.89 r90 top (schematic designator U3)
U3_Ch4 "INA821ID" D0008A_N 6658,5386.81 r90 top (schematic designator U3)
U3_Ch5 "INA821ID" D0008A_N 8613.7,5386.73 r90 top (schematic designator U3)
U3_Ch6 "INA821ID" D0008A_N 10175.7,5386.65 r90 top (schematic designator U3)
U3_Ch7 "INA821ID" D0008A_N 11737.7,5386.57 r90 top (schematic designator U3)
U3_Ch8 "INA821ID" D0008A_N 13299.7,5386.5 r90 top (schematic designator U3)
U4_Ch1 "INA190A1DCK" DCK0006A_N 2352,5557.05 r270 bottom (schematic designator U4)
U4_Ch2 "INA190A1DCK" DCK0006A_N 3914,5556.97 r270 bottom (schematic designator U4)
U4_Ch3 "INA190A1DCK" DCK0006A_N 5476,5556.89 r270 bottom (schematic designator U4)
U4_Ch4 "INA190A1DCK" DCK0006A_N 7038,5556.81 r270 bottom (schematic designator U4)
U4_Ch5 "INA190A1DCK" DCK0006A_N 8993.7,5556.73 r270 bottom (schematic designator U4)
U4_Ch6 "INA190A1DCK" DCK0006A_N 10555.7,5556.65 r270 bottom (schematic designator U4)
U4_Ch7 "INA190A1DCK" DCK0006A_N 12117.7,5556.57 r270 bottom (schematic designator U4)
U4_Ch8 "INA190A1DCK" DCK0006A_N 13679.7,5556.5 r270 bottom (schematic designator U4)
U5_Ch1 "TLV171IDBVR" DBV0005A_N 2035,5395.05 r270 bottom (schematic designator U5)
U5_Ch2 "TLV171IDBVR" DBV0005A_N 3597,5394.97 r270 bottom (schematic designator U5)
U5_Ch3 "TLV171IDBVR" DBV0005A_N 5159,5394.89 r270 bottom (schematic designator U5)
U5_Ch4 "TLV171IDBVR" DBV0005A_N 6721,5394.81 r270 bottom (schematic designator U5)
U5_Ch5 "TLV171IDBVR" DBV0005A_N 8676.7,5394.73 r270 bottom (schematic designator U5)
U5_Ch6 "TLV171IDBVR" DBV0005A_N 10238.7,5394.65 r270 bottom (schematic designator U5)
U5_Ch7 "TLV171IDBVR" DBV0005A_N 11800.7,5394.57 r270 bottom (schematic designator U5)
U5_Ch8 "TLV171IDBVR" DBV0005A_N 13362.7,5394.5 r270 bottom (schematic designator U5)
U6_Ch1 "TLV2171IDR" D0008A_N 2133,5956.05 r90 bottom (schematic designator U6)
U6_Ch2 "TLV2171IDR" D0008A_N 3695,5955.97 r90 bottom (schematic designator U6)
U6_Ch3 "TLV2171IDR" D0008A_N 5257,5955.89 r90 bottom (schematic designator U6)
U6_Ch4 "TLV2171IDR" D0008A_N 6819,5955.81 r90 bottom (schematic designator U6)
U6_Ch5 "TLV2171IDR" D0008A_N 8774.7,5955.73 r90 bottom (schematic designator U6)
U6_Ch6 "TLV2171IDR" D0008A_N 10336.7,5955.65 r90 bottom (schematic designator U6)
